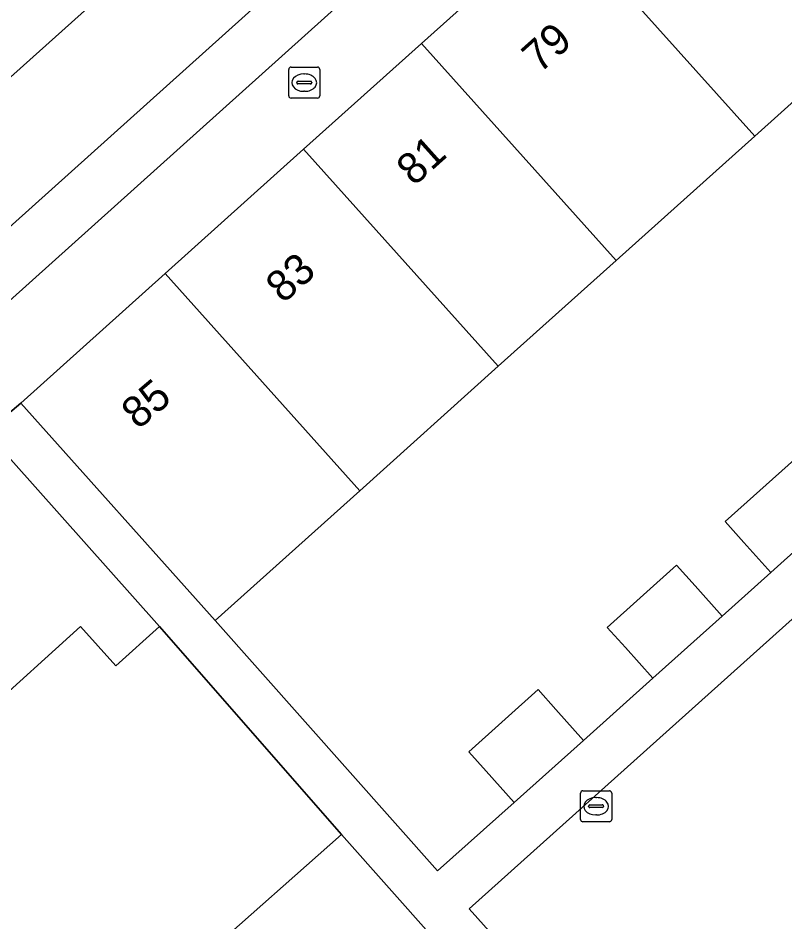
# Model space of a CAD drawing. Extents: x 162172 to 163187, y 382874 to 383685.
# Drawn here: x 162783.66 to 162808.38, y 383317.62 to 383346.73 of the extents above; entities that cross this region are included whole.
import ezdxf

# ---------------------------------------------------------------- set-up
doc = ezdxf.new("R2010")
doc.units = 0
for name, color, linetype in [('IMGEO_Berm_groen', 7, 'Continuous'), ('IMGEO_Brandkraan', 7, 'Continuous'), ('IMGEO_Erf', 7, 'Continuous'), ('IMGEO_Kolk', 7, 'Continuous'), ('IMGEO_Pand', 7, 'Continuous'), ('IMGEO_Pand_nummerreeks', 7, 'Continuous'), ('IMGEO_Parkeervlak_open', 7, 'Continuous'), ('IMGEO_Rijbaan_lokaal_open', 7, 'Continuous'), ('IMGEO_Voetpad_open', 7, 'Continuous')]:
    doc.layers.add(name, color=color, linetype=linetype)

msp = doc.modelspace()

# ---------------------------------------------------------------- linework, layer by layer
at = {"layer": 'IMGEO_Berm_groen'}
msp.add_lwpolyline([(162744.611, 383310), (162750.185, 383314.921), (162765.945, 383329.187), (162788.183, 383349.104), (162785.604, 383352.953), (162793.329, 383359.988), (162800.361, 383366.393), (162802.051, 383364.873), (162802.602, 383364.378)], dxfattribs=at)
at = {"layer": 'IMGEO_Brandkraan'}
for p, q in [((162792.461, 383345.151), (162793.313, 383345.151)), ((162792.386, 383344.225), (162792.386, 383345.077)), ((162792.874, 383344.931), (162792.899, 383344.931)), ((162793.387, 383345.077), (162793.387, 383344.225)), ((162792.645, 383344.645), (162792.645, 383344.657)), ((162793.083, 383344.608), (162792.685, 383344.608)), ((162792.688, 383344.694), (162793.086, 383344.694)), ((162793.129, 383344.657), (162793.129, 383344.645)), ((162792.897, 383344.371), (162792.872, 383344.371)), ((162793.313, 383344.151), (162792.461, 383344.151))]:
    msp.add_line(p, q, dxfattribs=at)
for points in [[(162792.461, 383345.151), (162793.313, 383345.151)], [(162792.386, 383344.225), (162792.386, 383345.077)], [(162793.387, 383345.077), (162793.387, 383344.225)], [(162793.313, 383344.151), (162792.461, 383344.151)]]:
    msp.add_lwpolyline(points, dxfattribs=at)
for centre, radius, start, end in [((162792.463, 383345.075), 0.0765, 91.552, 178.448), ((162792.463, 383345.075), 0.0765, 91.552, 178.448), ((162793.311, 383345.075), 0.0765, 1.552, 88.448), ((162793.311, 383345.075), 0.0765, 1.552, 88.448), ((162792.685, 383344.654), 0.0403, 85.8775, 175.7526), ((162792.682, 383344.644), 0.0366, 178.938, 274.7102), ((162793.086, 383344.651), 0.043, 264.8664, 352.4533), ((162793.09, 383344.656), 0.0386, 1.7309, 96.639), ((162792.463, 383344.227), 0.0765, 181.552, 268.448), ((162792.463, 383344.227), 0.0765, 181.552, 268.448), ((162793.311, 383344.227), 0.0765, 271.552, 358.448), ((162793.311, 383344.227), 0.0765, 271.552, 358.448)]:
    msp.add_arc(centre, radius, start, end, dxfattribs=at)
for centre, major_axis, ratio, start_param, end_param in [((162792.873, 383344.651), (-0.387, 0.002), 0.722429, 4.712389, 7.853982), ((162792.898, 383344.651), (-0.39, 0.002), 0.717154, 1.570796, 4.712389)]:
    msp.add_ellipse(centre, major_axis=major_axis, ratio=ratio, start_param=start_param, end_param=end_param, dxfattribs=at)
at = {"layer": 'IMGEO_Erf'}
for points in [[(162811.869, 383346.935), (162807.403, 383342.928), (162802.937, 383338.921), (162799.141, 383335.515), (162794.675, 383331.508), (162790.015, 383327.327), (162797.183, 383319.264), (162799.657, 383321.463), (162798.747, 383322.477), (162798.188, 383323.1), (162800.421, 383325.104), (162800.992, 383324.467), (162801.89, 383323.466), (162804.123, 383325.469), (162803.238, 383326.456), (162802.654, 383327.107), (162804.887, 383329.11), (162805.483, 383328.446), (162806.356, 383327.473), (162807.919, 383328.875), (162807.055, 383329.838), (162806.45, 383330.513), (162808.684, 383332.516)], [(162789.669, 383316.528), (162794.092, 383320.435), (162788.223, 383327.136), (162786.811, 383325.865), (162785.681, 383327.136), (162782.559, 383324.327), (162783.078, 383323.703), (162778.663, 383319.729), (162776.869, 383318.115), (162779.073, 383315.667)]]:
    msp.add_lwpolyline(points, dxfattribs=at)
at = {"layer": 'IMGEO_Kolk'}
for p, q in [((162801.868, 383321.845), (162802.72, 383321.845)), ((162801.793, 383320.919), (162801.793, 383321.771)), ((162802.281, 383321.625), (162802.306, 383321.625)), ((162802.794, 383321.771), (162802.794, 383320.919)), ((162802.052, 383321.339), (162802.052, 383321.351)), ((162802.49, 383321.302), (162802.092, 383321.302)), ((162802.095, 383321.388), (162802.493, 383321.388)), ((162802.536, 383321.351), (162802.536, 383321.339)), ((162802.304, 383321.065), (162802.279, 383321.065)), ((162802.72, 383320.845), (162801.868, 383320.845))]:
    msp.add_line(p, q, dxfattribs=at)
for points in [[(162801.868, 383321.845), (162802.72, 383321.845)], [(162801.793, 383320.919), (162801.793, 383321.771)], [(162802.794, 383321.771), (162802.794, 383320.919)], [(162802.72, 383320.845), (162801.868, 383320.845)]]:
    msp.add_lwpolyline(points, dxfattribs=at)
for centre, radius, start, end in [((162801.87, 383321.769), 0.0765, 91.552, 178.448), ((162801.87, 383321.769), 0.0765, 91.552, 178.448), ((162802.718, 383321.769), 0.0765, 1.552, 88.448), ((162802.718, 383321.769), 0.0765, 1.552, 88.448), ((162802.092, 383321.348), 0.0403, 85.8775, 175.7526), ((162802.089, 383321.338), 0.0366, 178.938, 274.7102), ((162802.493, 383321.345), 0.043, 264.8664, 352.4533), ((162802.497, 383321.35), 0.0386, 1.7309, 96.639), ((162801.87, 383320.921), 0.0765, 181.552, 268.448), ((162801.87, 383320.921), 0.0765, 181.552, 268.448), ((162802.718, 383320.921), 0.0765, 271.552, 358.448), ((162802.718, 383320.921), 0.0765, 271.552, 358.448)]:
    msp.add_arc(centre, radius, start, end, dxfattribs=at)
for centre, major_axis, ratio, start_param, end_param in [((162802.28, 383321.345), (-0.387, 0.002), 0.722429, 4.712389, 7.853982), ((162802.305, 383321.345), (-0.39, 0.002), 0.717154, 1.570796, 4.712389)]:
    msp.add_ellipse(centre, major_axis=major_axis, ratio=ratio, start_param=start_param, end_param=end_param, dxfattribs=at)
at = {"layer": 'IMGEO_Pand'}
for points in [[(162811.869, 383346.935), (162805.597, 383353.928), (162801.13, 383349.921), (162807.403, 383342.928)], [(162807.403, 383342.928), (162801.13, 383349.921), (162796.664, 383345.915), (162802.937, 383338.921)], [(162796.664, 383345.915), (162792.867, 383342.51), (162799.141, 383335.515), (162802.937, 383338.921)], [(162792.867, 383342.51), (162788.4, 383338.504), (162794.675, 383331.508), (162799.141, 383335.515)], [(162788.4, 383338.504), (162783.75, 383334.333), (162790.015, 383327.327), (162794.675, 383331.508)], [(162782.559, 383324.327), (162785.681, 383327.136), (162786.811, 383325.865), (162788.223, 383327.136), (162782.641, 383333.394), (162778.081, 383329.309)], [(162807.919, 383328.875), (162810.153, 383330.878), (162809.301, 383331.828), (162808.684, 383332.516), (162806.45, 383330.513), (162807.055, 383329.838)], [(162805.483, 383328.446), (162804.887, 383329.11), (162802.654, 383327.107), (162803.238, 383326.456), (162804.123, 383325.469), (162806.356, 383327.473)], [(162800.421, 383325.104), (162798.188, 383323.1), (162798.747, 383322.477), (162799.657, 383321.463), (162801.89, 383323.466), (162800.992, 383324.467)], [(162794.092, 383320.435), (162789.669, 383316.528), (162793.199, 383312.56), (162794.194, 383311.442), (162798.801, 383315.502), (162798.702, 383315.578), (162798.526, 383315.447)]]:
    msp.add_lwpolyline(points, close=True, dxfattribs=at)
at = {"layer": 'IMGEO_Parkeervlak_open'}
for points in [[(162843.693, 383394.145), (162811.886, 383365.593), (162808.297, 383362.372), (162752.534, 383312.314), (162752.272, 383312.079), (162752.63, 383312.208), (162753.767, 383312.366), (162754.785, 383312.353)], [(162755.461, 383312.558), (162842.607, 383390.811)]]:
    msp.add_lwpolyline(points, dxfattribs=at)
msp.add_lwpolyline([(162895.162, 383320.942), (162856.135, 383364.326), (162860.348, 383368.115), (162857.54, 383371.237), (162798.204, 383318.046), (162815.123, 383299.172), (162815.965, 383299.314), (162828.499, 383300.83), (162843.549, 383302.649), (162843.706, 383302.686), (162843.036, 383308.139), (162851.601, 383309.192), (162857.334, 383309.83), (162865.781, 383310.872), (162866.43, 383305.611), (162891.656, 383308.468), (162894.87, 383308.939), (162900.797, 383313.985), (162901.094, 383314.238)], close=True, dxfattribs=at)
at = {"layer": 'IMGEO_Rijbaan_lokaal_open'}
msp.add_lwpolyline([(162752.534, 383312.314), (162808.297, 383362.372), (162805.798, 383364.945), (162788.183, 383349.104), (162765.945, 383329.187), (162750.185, 383314.921)], close=True, dxfattribs=at)
at = {"layer": 'IMGEO_Voetpad_open'}
for points in [[(162842.607, 383390.811), (162755.461, 383312.558)], [(162851.601, 383309.192), (162843.036, 383308.139), (162843.706, 383302.686), (162843.549, 383302.649), (162828.499, 383300.83), (162815.965, 383299.314), (162815.123, 383299.172), (162798.204, 383318.046), (162857.54, 383371.237)], [(162763.413, 383316.169), (162766.792, 383319.195), (162770.039, 383322.104), (162773.633, 383325.324), (162778.081, 383329.309), (162782.641, 383333.394), (162783.75, 383334.333), (162788.4, 383338.504), (162792.867, 383342.51), (162796.664, 383345.915), (162801.13, 383349.921), (162805.597, 383353.928), (162810.063, 383357.934)], [(162810.153, 383330.878), (162807.919, 383328.875), (162806.356, 383327.473), (162804.123, 383325.469), (162801.89, 383323.466), (162799.657, 383321.463), (162797.183, 383319.264), (162790.015, 383327.327), (162783.75, 383334.333), (162782.641, 383333.394), (162788.223, 383327.136), (162794.092, 383320.435), (162798.526, 383315.447), (162798.702, 383315.578), (162798.801, 383315.502), (162800.173, 383313.968), (162806.783, 383306.582), (162813.788, 383298.759)]]:
    msp.add_lwpolyline(points, dxfattribs=at)

# ---------------------------------------------------------------- texts
at = {"layer": 'IMGEO_Pand_nummerreeks'}
for s, rotation, p in [('79', 41.8897, (162800.472, 383344.925)), ('81', 41.8897, (162796.425, 383341.295)), ('83', 41.8897, (162792.211, 383337.515)), ('85', 40.4781, (162787.537, 383333.455))]:
    msp.add_text(s, height=1, rotation=rotation, dxfattribs=at).set_placement(p)

doc.saveas('drawing.dxf')
